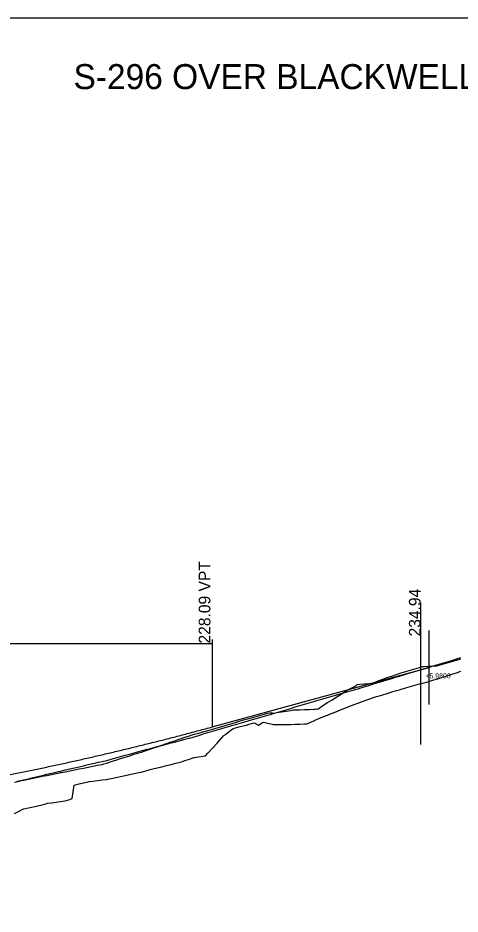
# Model space of a CAD drawing. Extents: x 2224795 to 2228395, y 930927 to 933127.
# Drawn here: x 2226814 to 2227079, y 932017 to 932554 of the extents above; entities that cross this region are included whole.
import ezdxf

# ---------------------------------------------------------------- set-up
doc = ezdxf.new("R2010")
doc.units = 0
for name, color, linetype in [('BR_EXIST_GROUND_LT', 7, 'Continuous'), ('BR_EXIST_GROUND_RT', 7, 'Continuous'), ('BR_USER NOTES', 7, 'Continuous'), ('RD_DDB_Profile_EX', 7, 'Continuous'), ('RD_DDB_Profile_Lbl', 7, 'Continuous'), ('RD_DDB_Profile_PR', 7, 'Continuous'), ('RD_DDB_StripGrade', 7, 'Continuous'), ('RD_DDB_VCLbl', 7, 'Continuous'), ('RD_SHT_ShtClip', 7, 'Continuous'), ('RD_SHT_TX', 7, 'Continuous')]:
    doc.layers.add(name, color=color, linetype=linetype)

msp = doc.modelspace()

# ---------------------------------------------------------------- linework, layer by layer
at = {"layer": 'BR_EXIST_GROUND_LT'}
msp.add_lwpolyline([(2226811.74, 932076.9), (2226814.49, 932078.43), (2226816.63, 932079.63), (2226817.25, 932079.75), (2226820.01, 932080.32), (2226822.77, 932080.93), (2226825.53, 932081.58), (2226828.28, 932082.26), (2226831.04, 932082.99), (2226831.47, 932083.11), (2226833.8, 932083.39), (2226836.56, 932083.76), (2226839.31, 932084.16), (2226842.11, 932084.59), (2226844.83, 932085.48), (2226846.23, 932085.96), (2226847.32, 932094.01), (2226850.34, 932094.72), (2226853.1, 932095.37), (2226855.86, 932096.03), (2226856.32, 932096.14), (2226858.62, 932096.42), (2226861.38, 932096.76), (2226864.13, 932097.11), (2226866.89, 932097.47), (2226867.53, 932097.57), (2226869.65, 932098), (2226872.41, 932098.57), (2226875.16, 932099.14), (2226877.92, 932099.73), (2226880.68, 932100.32), (2226883.44, 932100.92), (2226886.2, 932101.53), (2226887.51, 932101.83), (2226888.95, 932102.24), (2226891.71, 932103.04), (2226892.96, 932103.41), (2226894.47, 932103.76), (2226897.23, 932104.41), (2226899.98, 932105.07), (2226902.74, 932105.74), (2226905.5, 932106.42), (2226908.26, 932107.12), (2226911.02, 932107.83), (2226911.74, 932108.01), (2226913.77, 932108.7), (2226916.53, 932109.66), (2226918.49, 932110.34), (2226918.84, 932110.44), (2226919.29, 932110.51), (2226922.05, 932110.94), (2226924.8, 932111.39), (2226926.17, 932111.63), (2226927.56, 932113.14), (2226930.32, 932116.18), (2226933.08, 932119.26), (2226935.84, 932122.38), (2226936.83, 932123.51), (2226937.18, 932123.71), (2226937.95, 932124.26), (2226938.59, 932124.77), (2226941.35, 932126.94), (2226942.65, 932127.97), (2226944.11, 932128.46), (2226946.87, 932129.1), (2226949.62, 932129.74), (2226950.76, 932130), (2226952.38, 932130.57), (2226953.76, 932131.06), (2226955.3, 932131.37), (2226957.9, 932129.99), (2226960.65, 932131.7), (2226963.41, 932131.11), (2226966.17, 932130.54), (2226966.97, 932130.38), (2226968.93, 932130.37), (2226971.69, 932130.39), (2226974.44, 932130.42), (2226977.2, 932130.46), (2226979.96, 932130.52), (2226982.72, 932130.6), (2226985.47, 932130.69), (2226986.99, 932130.75), (2226988.23, 932131.32), (2226990.99, 932132.57), (2226991.72, 932132.9), (2226993.75, 932133.75), (2226996.51, 932134.88), (2226999.26, 932136.01), (2227002.02, 932137.12), (2227004.78, 932138.21), (2227005.18, 932138.37), (2227007.54, 932139.32), (2227010.29, 932140.42), (2227013.05, 932141.51), (2227015.81, 932142.58), (2227016.87, 932142.99), (2227018.57, 932143.62), (2227020.06, 932144.16), (2227021.33, 932144.61), (2227024.08, 932145.57), (2227026.84, 932146.52), (2227028.7, 932147.15), (2227029.6, 932147.42), (2227032.36, 932148.24), (2227035.11, 932149.06), (2227037.87, 932149.88), (2227040.63, 932150.69), (2227042.45, 932151.22), (2227043.39, 932151.5), (2227046.14, 932152.3), (2227048.9, 932153.1), (2227051.66, 932153.89), (2227054.42, 932154.68), (2227057.18, 932155.46), (2227059.93, 932156.24), (2227062.98, 932157.1), (2227065.45, 932157.8), (2227068.21, 932158.72), (2227070.96, 932159.64), (2227073.72, 932160.55), (2227076.48, 932161.47), (2227079.24, 932162.37)], dxfattribs=at)
at = {"layer": 'BR_EXIST_GROUND_RT'}
msp.add_lwpolyline([(2226811.74, 932095.82), (2226814.49, 932096.48), (2226815.43, 932096.7), (2226817.25, 932097.07), (2226820.01, 932097.63), (2226822.77, 932098.19), (2226825.53, 932098.75), (2226828.28, 932099.31), (2226831.04, 932099.86), (2226833.8, 932100.42), (2226836.56, 932100.97), (2226838.91, 932101.44), (2226839.31, 932101.5), (2226839.69, 932101.55), (2226842.07, 932102.03), (2226844.83, 932102.58), (2226847.59, 932103.14), (2226850.34, 932103.69), (2226853.1, 932104.24), (2226855.86, 932104.8), (2226858.62, 932105.35), (2226861.38, 932105.9), (2226864.22, 932106.47), (2226864.79, 932106.58), (2226865.28, 932106.75), (2226866.89, 932107.26), (2226869.65, 932108.14), (2226872.41, 932109.02), (2226875.16, 932109.9), (2226877.92, 932110.78), (2226880.68, 932111.65), (2226883.44, 932112.53), (2226886.2, 932113.4), (2226887.73, 932113.88), (2226889.35, 932114.42), (2226891.71, 932115.21), (2226894.47, 932116.14), (2226897.23, 932117.08), (2226899.98, 932118.02), (2226902.74, 932118.97), (2226905.5, 932119.92), (2226908.26, 932120.88), (2226910.23, 932121.57), (2226911.02, 932121.82), (2226913.8, 932122.71), (2226914.52, 932122.94), (2226916.53, 932123.63), (2226918.23, 932124.22), (2226919.29, 932124.51), (2226922.05, 932125.25), (2226924.4, 932125.89), (2226924.8, 932126), (2226927.56, 932126.8), (2226930.32, 932127.6), (2226933.08, 932128.41), (2226935.84, 932129.22), (2226938.59, 932130.03), (2226941.35, 932130.84), (2226942.65, 932131.23), (2226944.11, 932131.66), (2226946.87, 932132.49), (2226949.62, 932133.31), (2226952.38, 932134.07), (2226955.14, 932134.83), (2226957.9, 932135.59), (2226960.65, 932136.36), (2226963.41, 932137.13), (2226964.41, 932137.41), (2226966.17, 932137.28), (2226967.05, 932137.22), (2226968.93, 932137.51), (2226971.69, 932137.94), (2226974.44, 932138.38), (2226977.2, 932138.83), (2226978.83, 932139.1), (2226979.96, 932139.13), (2226982.72, 932139.21), (2226985.47, 932139.3), (2226988.23, 932139.41), (2226990.99, 932139.54), (2226991.82, 932139.58), (2226992.69, 932139.71), (2226993.48, 932139.66), (2226996.51, 932141.68), (2226999.26, 932143.49), (2227002.02, 932145.25), (2227004.78, 932146.97), (2227007.54, 932148.65), (2227010.29, 932150.29), (2227013.05, 932151.9), (2227015.81, 932153.46), (2227016.11, 932153.63), (2227016.59, 932154.06), (2227017.12, 932154.36), (2227018.57, 932154.53), (2227021.33, 932154.81), (2227024.08, 932155.05), (2227026.27, 932155.2), (2227026.84, 932155.43), (2227029.6, 932156.48), (2227032.36, 932157.5), (2227035.11, 932158.49), (2227037.87, 932159.45), (2227040.63, 932160.39), (2227041.57, 932160.7), (2227043.39, 932161.29), (2227046.14, 932162.17), (2227048.9, 932163.02), (2227051.66, 932163.84), (2227054.42, 932164.63), (2227056.47, 932165.19), (2227057.18, 932165.24), (2227059.93, 932165.39), (2227062.69, 932165.53), (2227065.02, 932165.63), (2227065.45, 932165.76), (2227068.21, 932166.62), (2227070.96, 932167.45), (2227073.72, 932168.26), (2227076.48, 932169.05), (2227079.24, 932169.82)], dxfattribs=at)
at = {"layer": 'BR_USER NOTES'}
for p, q in [((2227055.06, 932203.42), (2227055.06, 932118.37)), ((2227060.06, 932186.71), (2227060.06, 932142.39)), ((2227055.06, 932163.2), (2227060.06, 932164.7))]:
    msp.add_line(p, q, dxfattribs=at)
at = {"layer": 'RD_DDB_Profile_EX'}
msp.add_lwpolyline([(2226813.08, 932096.24), (2226814.49, 932096.51), (2226815.1, 932096.62), (2226817.25, 932097.15), (2226820.01, 932097.82), (2226822.77, 932098.5), (2226825.53, 932099.16), (2226828.28, 932099.83), (2226831.04, 932100.49), (2226833.8, 932101.14), (2226836.56, 932101.79), (2226838.01, 932102.13), (2226839.31, 932102.46), (2226840.07, 932102.65), (2226842.07, 932103.12), (2226844.83, 932103.76), (2226847.59, 932104.4), (2226850.34, 932105.04), (2226853.1, 932105.67), (2226855.86, 932106.29), (2226858.62, 932106.92), (2226861.38, 932107.54), (2226862.09, 932107.7), (2226864.13, 932108.19), (2226865.05, 932108.41), (2226866.27, 932108.68), (2226866.89, 932108.86), (2226869.65, 932109.63), (2226872.41, 932110.39), (2226875.16, 932111.15), (2226877.92, 932111.91), (2226880.68, 932112.67), (2226883.44, 932113.42), (2226886.2, 932114.17), (2226888.95, 932114.92), (2226891.21, 932115.54), (2226891.71, 932115.68), (2226894.47, 932116.42), (2226897.23, 932117.15), (2226899.98, 932117.88), (2226902.74, 932118.61), (2226905.5, 932119.34), (2226908.26, 932120.06), (2226911.02, 932120.78), (2226913.08, 932121.32), (2226913.77, 932121.51), (2226916.2, 932122.15), (2226916.53, 932122.24), (2226918.13, 932122.65), (2226919.29, 932123.02), (2226920.68, 932123.47), (2226922.05, 932123.88), (2226924.8, 932124.7), (2226927.56, 932125.52), (2226930.32, 932126.34), (2226933.08, 932127.15), (2226935.84, 932127.96), (2226938.59, 932128.77), (2226941.35, 932129.58), (2226942.43, 932129.89), (2226944.34, 932130.48), (2226946.87, 932131.21), (2226949.62, 932132.01), (2226952.38, 932132.8), (2226955.14, 932133.59), (2226957.9, 932134.38), (2226960.65, 932135.16), (2226963.41, 932135.95), (2226965.27, 932136.47), (2226966.17, 932136.75), (2226968.93, 932137.58), (2226971.69, 932138.41), (2226974.44, 932139.24), (2226977.2, 932140.07), (2226979.96, 932140.89), (2226982.72, 932141.71), (2226985.47, 932142.53), (2226988.23, 932143.34), (2226990.99, 932144.16), (2226992.34, 932144.55), (2226993.75, 932144.96), (2226996.51, 932145.77), (2226999.26, 932146.57), (2227002.02, 932147.37), (2227004.78, 932148.17), (2227007.54, 932148.96), (2227010.29, 932149.76), (2227013.05, 932150.55), (2227015.45, 932151.23), (2227015.81, 932151.34), (2227017.62, 932151.86), (2227017.98, 932151.96), (2227018.57, 932152.14), (2227021.33, 932152.99), (2227024.08, 932153.84), (2227026.84, 932154.68), (2227029.6, 932155.52), (2227032.36, 932156.36), (2227035.11, 932157.2), (2227037.87, 932158.04), (2227040.63, 932158.88), (2227042.54, 932159.45), (2227043.39, 932159.7), (2227044.41, 932160), (2227046.14, 932160.53), (2227048.9, 932161.36), (2227051.66, 932162.18), (2227054.42, 932163.01), (2227057.18, 932163.84), (2227059.93, 932164.66), (2227062.69, 932165.48), (2227065.45, 932166.3), (2227067.58, 932166.93), (2227068.21, 932167.13), (2227070.96, 932168), (2227073.72, 932168.87), (2227076.48, 932169.74), (2227079.24, 932170.61)], dxfattribs=at)
at = {"layer": 'RD_DDB_Profile_PR'}
msp.add_line((2226930.06, 932128.95), (2227055.06, 932163.2), dxfattribs=at)
msp.add_spline([(2226530.06, 932069.15), (2226538.06, 932069.37), (2226546.06, 932069.63), (2226554.06, 932069.93), (2226562.06, 932070.27), (2226570.06, 932070.65), (2226578.06, 932071.07), (2226586.06, 932071.53), (2226594.06, 932072.03), (2226602.06, 932072.57), (2226610.06, 932073.15), (2226618.06, 932073.76), (2226626.06, 932074.42), (2226634.06, 932075.12), (2226642.06, 932075.86), (2226650.06, 932076.64), (2226658.06, 932077.45), (2226666.06, 932078.31), (2226674.06, 932079.21), (2226682.06, 932080.15), (2226690.06, 932081.12), (2226698.06, 932082.14), (2226706.06, 932083.2), (2226714.06, 932084.29), (2226722.06, 932085.43), (2226730.06, 932086.6), (2226738.06, 932087.82), (2226746.06, 932089.08), (2226754.06, 932090.37), (2226762.06, 932091.71), (2226770.06, 932093.08), (2226778.06, 932094.5), (2226786.06, 932095.95), (2226794.06, 932097.45), (2226802.06, 932098.98), (2226810.06, 932100.56), (2226818.06, 932102.17), (2226826.06, 932103.82), (2226834.06, 932105.52), (2226842.06, 932107.25), (2226850.06, 932109.03), (2226858.06, 932110.84), (2226866.06, 932112.69), (2226874.06, 932114.59), (2226882.06, 932116.52), (2226890.06, 932118.49), (2226898.06, 932120.5), (2226906.06, 932122.56), (2226914.06, 932124.65), (2226922.06, 932126.78), (2226930.06, 932128.95)], degree=3, dxfattribs=at)
at = {"layer": 'RD_DDB_VCLbl'}
for p, q in [((2226530.06, 932178.95), (2226930.06, 932178.95)), ((2226930.06, 932181.45), (2226930.06, 932128.95))]:
    msp.add_line(p, q, dxfattribs=at)
at = {"layer": 'RD_SHT_ShtClip'}
msp.add_lwpolyline([(2225474.62, 932554.3), (2227274.62, 932554.3), (2227274.62, 931454.3), (2225474.62, 931454.3)], close=True, dxfattribs=at)

# ---------------------------------------------------------------- texts
at = {"layer": 'BR_USER NOTES'}
msp.add_text('+5.9800', height=3, dxfattribs=at).set_placement((2227058, 932158.03))
at = {"layer": 'RD_DDB_Profile_Lbl'}
msp.add_text('234.94', height=7, rotation=90, dxfattribs=at).set_placement((2227055.06, 932183.2))
at = {"layer": 'RD_DDB_StripGrade'}
msp.add_text('228.09 VPT', height=7, rotation=90, dxfattribs=at).set_placement((2226929.06, 932178.95))
at = {"layer": 'RD_SHT_TX'}
msp.add_text('S-296 OVER BLACKWELL MILL STREAM', height=15, rotation=360, dxfattribs=at).set_placement((2226847.02, 932511.59))

doc.saveas('drawing.dxf')
